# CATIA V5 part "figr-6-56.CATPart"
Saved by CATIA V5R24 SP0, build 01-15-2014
Part number: Part1
Bounding box of the stored display mesh (mm): x -50.648 to 50.648, y -72.183 to 72.183, z 0 to 52
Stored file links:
  D:\KAVITA\CATIA V5-6R2014 Project_ Kavita\CATIA V5-6R2014_partfiles\Partfiles\c06_catia_v5-6r2014_prt\figr-6-56.CATPart
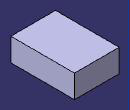
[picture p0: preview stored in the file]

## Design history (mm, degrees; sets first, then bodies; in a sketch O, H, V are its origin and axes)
Body1 (main body)
  Sketch1 on xy-plane, origin (0, 0, 0), H (1, 0, 0), V (0, 1, 0)
    line L1 (-50.6478, 72.1832) -> (50.6478, 72.1832)
    line L2 (50.6478, 72.1832) -> (50.6478, -72.1832)
    line L3 (50.6478, -72.1832) -> (-50.6478, -72.1832)
    line L4 (-50.6478, -72.1832) -> (-50.6478, 72.1832)
    axis line L5 (50.6478, -72.1832) -> (-50.6478, 72.1832)
    horizontal: L1 H, L3 H
    vertical: L2 V, L4 V
    midpoint: O L5
  Pad1: profile Sketch1, direction (0, 0, 1), length 52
